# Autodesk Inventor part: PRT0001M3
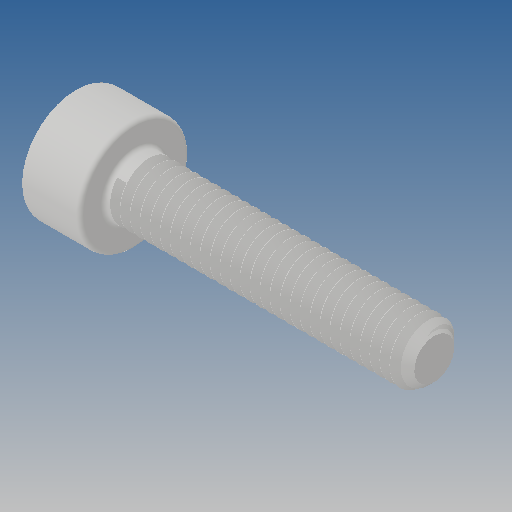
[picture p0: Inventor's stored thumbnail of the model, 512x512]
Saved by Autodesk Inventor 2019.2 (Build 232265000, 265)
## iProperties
Created: 2010-02
Part Number: PRT0001M3
Material: Ogólny
Document SubType Name: Modeling
Designer: CADENGINEERING4
Density: 1 g/cm^3
Appearance: Domyślna
Author: CADENGINEERING4
Revision Number: 1LAST_VERSION
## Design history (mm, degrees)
feature "Baza1"
node "Bryła1"
